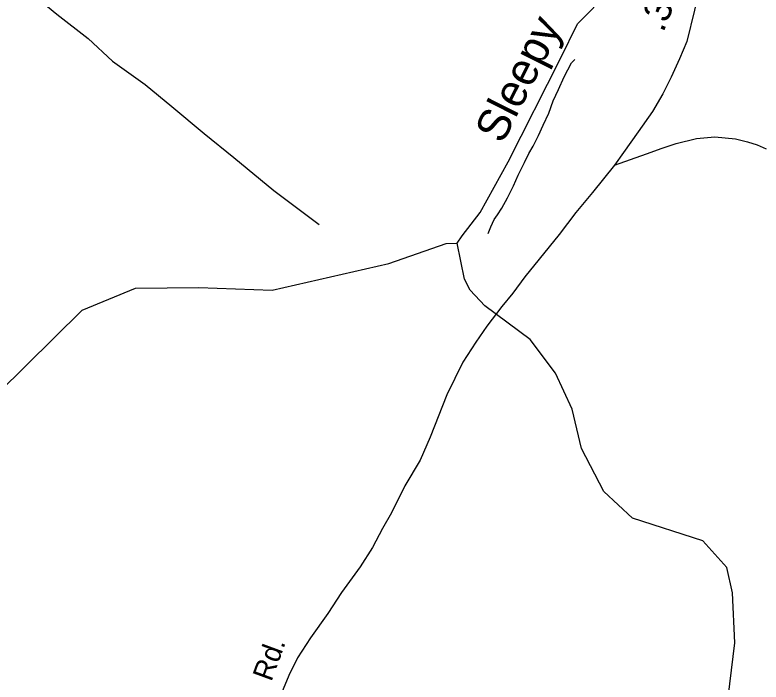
# Model space of a CAD drawing. Extents: x 2206922 to 2357709, y 510027 to 673830.
# Drawn here: x 2309278 to 2312734, y 544730 to 547820 of the extents above; entities that cross this region are included whole.
import ezdxf

# ---------------------------------------------------------------- set-up
doc = ezdxf.new("R2010")
doc.units = 0
for name, color, linetype in [('Exist Hydrographic Creek Single Shore', 7, 'Continuous'), ('Exist Hydrographic Creek Single Shore Label', 7, 'Continuous'), ('Exist Hydrographic Misc Water Feature', 7, 'Continuous'), ('Exist Road Non-System Type 51', 7, 'Continuous'), ('Exist Road Secondary Mileage Hundredths English Label', 7, 'Continuous'), ('Exist Road Secondary Type 51 Attributed', 7, 'Continuous'), ('Exist Road Secondary Type 51 Label', 7, 'Continuous')]:
    doc.layers.add(name, color=color, linetype=linetype)

msp = doc.modelspace()

# ---------------------------------------------------------------- linework, layer by layer
at = {"layer": 'Exist Hydrographic Creek Single Shore'}
for points in [[(2311805.6, 547619), (2311883.3, 547779.5), (2312032.4, 547929.9), (2312048.4, 548006)], [(2311326.4, 546762.7), (2311350.4, 546796.6), (2311433.4, 546904.9), (2311563.4, 547139.8), (2311805.6, 547619)], [(2308166.3, 544778), (2308190.3, 544805.2), (2308397.2, 544931.7), (2308479.2, 545033.4), (2308586.3, 545234.6), (2308675.3, 545467.9), (2308706.2, 545659.5), (2308755.2, 545753.3), (2308837.2, 545819), (2309069.4, 545939.9), (2309589.4, 546453.1), (2309837.3, 546555.1), (2310129.3, 546556.9), (2310470.3, 546544.5), (2311010.4, 546668), (2311276.3, 546760.7), (2311326.4, 546762.7)], [(2312574.3, 544594.7), (2312612.5, 544911.3), (2312601.4, 545143.8), (2312575.3, 545260.9), (2312465.4, 545384.5), (2312139.4, 545489.4), (2312005.3, 545612), (2311902.4, 545811.3), (2311859.3, 545993.4), (2311782.4, 546160.9), (2311664.3, 546316.9), (2311454.3, 546472.5), (2311387.3, 546545.3), (2311361.2, 546596.8), (2311326.4, 546762.7)]]:
    msp.add_lwpolyline(points, dxfattribs=at)
at = {"layer": 'Exist Hydrographic Misc Water Feature'}
msp.add_lwpolyline([(2311470.5, 546807.8), (2311482.2, 546838.1), (2311497.8, 546872.3), (2311513.8, 546894.2), (2311533.3, 546924.5), (2311559.1, 546972.5), (2311588, 547029), (2311609.8, 547077.2), (2311639.3, 547137.2), (2311658.8, 547177.7), (2311678, 547211.7), (2311703.7, 547262.2), (2311725, 547310.1), (2311750.6, 547364.6), (2311771.7, 547422.6), (2311795.3, 547475.1), (2311822.4, 547533.4), (2311855.6, 547597.4), (2311871.4, 547613.6)], dxfattribs=at)
at = {"layer": 'Exist Road Non-System Type 51'}
msp.add_lwpolyline([(2309298.8, 547971.3), (2309342, 547931.7), (2309472.7, 547823.1), (2309618, 547710.8), (2309730.3, 547605.8), (2309881.2, 547498.1), (2310005.4, 547395.9), (2310154.4, 547271.6), (2310291.5, 547160.3), (2310477.4, 547006.5), (2310687.1, 546849.1)], dxfattribs=at)
at = {"layer": 'Exist Road Secondary Type 51 Attributed'}
for points in [[(2312496.1, 548270.1), (2312492, 548164.9), (2312473, 548046.9), (2312447.8, 547937.4), (2312426.7, 547842.6), (2312391, 547697.1), (2312357.3, 547617.3), (2312318.7, 547532.3), (2312279.4, 547453.9), (2312232.2, 547373.4), (2312165.4, 547278.9), (2312096.5, 547182.5), (2312054.7, 547124.4)], [(2312054.7, 547124.4), (2312203.5, 547177), (2312276.1, 547202.4), (2312341.5, 547224.2), (2312434.9, 547247.8), (2312520.2, 547255.1), (2312615.5, 547246), (2312670.8, 547231.5), (2312715.8, 547218.8), (2312758, 547200.6)], [(2312054.7, 547124.4), (2311954, 546997.3), (2311876, 546904.7), (2311799.7, 546803), (2311707.2, 546688.6), (2311640, 546606.9), (2311583.8, 546530.6), (2311533, 546468.9), (2311464, 546378.1), (2311413.2, 546303.6), (2311353.3, 546211), (2311278.9, 546060.3), (2311200.9, 545864.2), (2311155.5, 545757.1), (2311084.7, 545639), (2311023, 545513.8), (2310981.3, 545441.1), (2310934.1, 545354), (2310877.8, 545263.2), (2310790.7, 545145.1), (2310727.2, 545047.1), (2310647.3, 544934.5), (2310587.5, 544841.9), (2310547.5, 544760.2), (2310440.2, 544503.8)]]:
    msp.add_lwpolyline(points, dxfattribs=at)

# ---------------------------------------------------------------- texts
at = {"layer": 'Exist Hydrographic Creek Single Shore Label'}
msp.add_text('Sleepy', height=150, rotation=63.1903, dxfattribs=at).set_placement((2311536.4, 547217.9))
at = {"layer": 'Exist Road Secondary Mileage Hundredths English Label'}
msp.add_text('.33', height=125, rotation=68.2931, dxfattribs=at).set_placement((2312281.3, 547735.6))
at = {"layer": 'Exist Road Secondary Type 51 Label'}
msp.add_text('Rd.', height=95, rotation=69.8511, dxfattribs=at).set_placement((2310465.7, 544728.6))

doc.saveas('drawing.dxf')
